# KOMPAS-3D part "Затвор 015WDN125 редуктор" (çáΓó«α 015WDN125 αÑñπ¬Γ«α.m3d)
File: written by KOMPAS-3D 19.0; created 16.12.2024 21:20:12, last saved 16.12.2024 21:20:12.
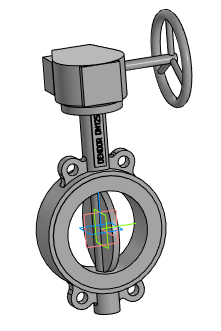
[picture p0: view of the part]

Document properties: Автор: Евгений; Полное имя файла: ..\Затвор 015WDN125 редуктор.a3d

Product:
- Part/product: Затвор 015WDN125 редуктор
    Масса: 15.8315

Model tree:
1. Операция без истории:1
